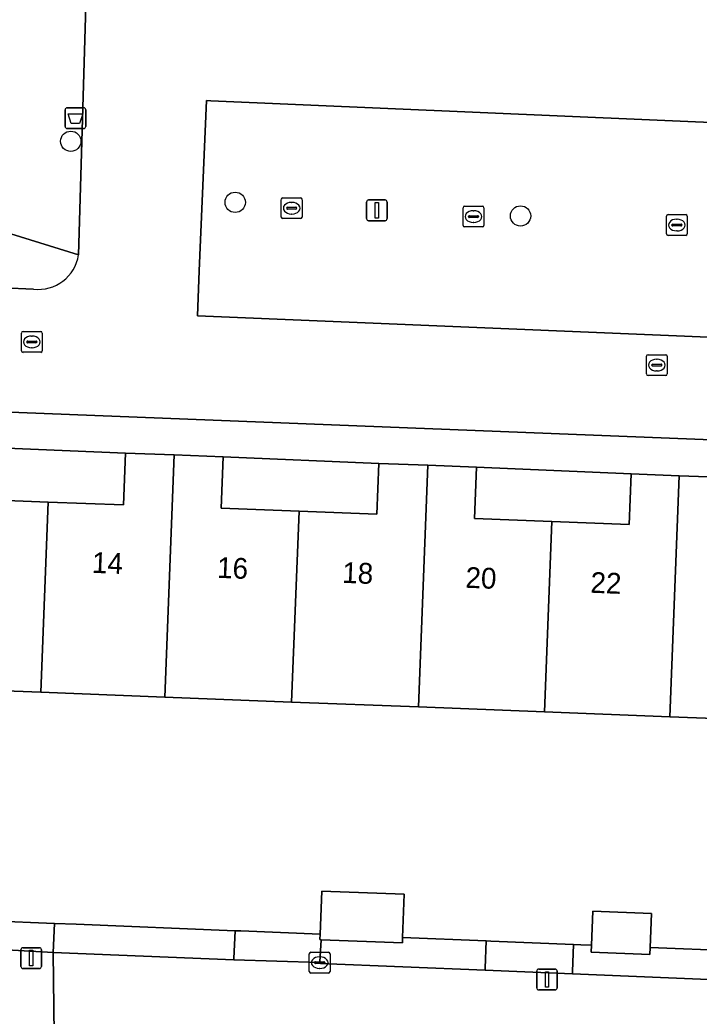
# Model space of a CAD drawing. Extents: x 160786 to 161429, y 386828 to 387485.
# Drawn here: x 161040.54 to 161073.22, y 387264.64 to 387312.56 of the extents above; entities that cross this region are included whole.
import ezdxf

# ---------------------------------------------------------------- set-up
doc = ezdxf.new("R2010")
doc.units = 0
for name, color, linetype in [('IMGEO_Afvalbak', 7, 'Continuous'), ('IMGEO_Boom', 7, 'Continuous'), ('IMGEO_Erf', 7, 'Continuous'), ('IMGEO_Groenvoorziening', 7, 'Continuous'), ('IMGEO_Kolk', 7, 'Continuous'), ('IMGEO_Lichtmast', 7, 'Continuous'), ('IMGEO_Pand', 7, 'Continuous'), ('IMGEO_Pand_nummerreeks', 7, 'Continuous'), ('IMGEO_Parkeervlak_open', 7, 'Continuous'), ('IMGEO_Rioolput', 7, 'Continuous'), ('IMGEO_Voetpad_open', 7, 'Continuous')]:
    doc.layers.add(name, color=color, linetype=linetype)

msp = doc.modelspace()

# ---------------------------------------------------------------- linework, layer by layer
at = {"layer": 'IMGEO_Afvalbak'}
for p, q in [((161042.718, 387307.44), (161042.718, 387308.24)), ((161042.718, 387308.24), (161042.718, 387307.44)), ((161042.818, 387308.34), (161043.608, 387308.34)), ((161043.608, 387308.34), (161042.818, 387308.34)), ((161043.708, 387308.24), (161043.708, 387307.44)), ((161043.708, 387307.44), (161043.708, 387308.24)), ((161043.608, 387307.34), (161042.818, 387307.34)), ((161042.818, 387307.34), (161043.608, 387307.34))]:
    msp.add_line(p, q, dxfattribs=at)
msp.add_lwpolyline([(161042.861, 387308.054), (161043.565, 387308.054), (161043.416, 387307.584), (161043.01, 387307.584), (161042.861, 387308.054)], dxfattribs=at)
for centre, start, end in [((161042.818, 387308.24), 90, 180), ((161042.818, 387308.24), 90, 180), ((161043.608, 387308.24), 0, 90), ((161043.608, 387308.24), 360, 90), ((161042.818, 387307.44), 180, 270), ((161042.818, 387307.44), 180, 270), ((161043.608, 387307.44), 270, 0), ((161043.608, 387307.44), 270, 0)]:
    msp.add_arc(centre, 0.1, start, end, dxfattribs=at)
at = {"layer": 'IMGEO_Boom'}
for centre in [(161042.988, 387306.725), (161050.899, 387303.788), (161064.629, 387303.133)]:
    msp.add_circle(centre, 0.489, dxfattribs=at)
at = {"layer": 'IMGEO_Erf'}
for points in [[(161038.374, 387292.034), (161038.276, 387289.514), (161041.898, 387289.372), (161045.518, 387289.231), (161045.615, 387291.726)], [(161050.318, 387291.542), (161050.222, 387289.075), (161053.97, 387288.928), (161057.718, 387288.782), (161057.814, 387291.229)], [(161062.516, 387291.045), (161062.42, 387288.576), (161066.138, 387288.431), (161069.857, 387288.286), (161069.952, 387290.729)]]:
    msp.add_lwpolyline(points, close=True, dxfattribs=at)
for points in [[(161101.692, 387277.875), (161095.739, 387278.107), (161089.782, 387278.339), (161083.812, 387278.572), (161077.787, 387278.807), (161071.808, 387279.04), (161065.781, 387279.275), (161059.712, 387279.512), (161053.612, 387279.75), (161047.514, 387279.988), (161041.541, 387280.221), (161035.537, 387280.455), (161035.313, 387280.464), (161035.188, 387277.258), (161029.377, 387277.484), (161029.502, 387280.69), (161023.521, 387280.923), (161017.529, 387281.157), (161011.527, 387281.391), (161011.389, 387277.862), (161005.238, 387278.102), (161005.045, 387271.345)], [(161039.126, 387269.225), (161042.204, 387269.1), (161043.253, 387269.058), (161050.892, 387268.747), (161051.177, 387268.736), (161054.984, 387268.581), (161055.065, 387270.654), (161059.035, 387270.499), (161058.953, 387268.42), (161062.977, 387268.257), (161063.197, 387268.248), (161067.18, 387268.086), (161067.524, 387268.072), (161068.036, 387268.051), (161068.1, 387269.689), (161070.927, 387269.579), (161070.863, 387267.936), (161074.883, 387267.773)]]:
    msp.add_lwpolyline(points, dxfattribs=at)
at = {"layer": 'IMGEO_Groenvoorziening'}
for points in [[(161050.892, 387268.747), (161043.253, 387269.058), (161042.204, 387269.1), (161042.15, 387267.701), (161050.837, 387267.344), (161050.84, 387267.414)], [(161062.977, 387268.257), (161058.953, 387268.42), (161058.943, 387268.163), (161055.037, 387268.316), (161054.968, 387267.254), (161054.965, 387267.213), (161055, 387267.174), (161062.922, 387266.848), (161062.926, 387266.944)], [(161074.883, 387267.773), (161070.863, 387267.936), (161070.85, 387267.611), (161068.023, 387267.721), (161068.036, 387268.051), (161067.524, 387268.072), (161067.18, 387268.086), (161067.127, 387266.78), (161067.122, 387266.676), (161074.828, 387266.36), (161074.832, 387266.481)]]:
    msp.add_lwpolyline(points, close=True, dxfattribs=at)
at = {"layer": 'IMGEO_Kolk'}
for p, q in [((161053.117, 387303.081), (161053.117, 387303.933)), ((161053.192, 387304.007), (161054.044, 387304.007)), ((161054.118, 387303.933), (161054.118, 387303.081)), ((161053.376, 387303.501), (161053.376, 387303.513)), ((161053.814, 387303.464), (161053.416, 387303.464)), ((161053.419, 387303.55), (161053.817, 387303.55)), ((161053.605, 387303.787), (161053.63, 387303.787)), ((161053.86, 387303.513), (161053.86, 387303.501)), ((161061.864, 387302.677), (161061.864, 387303.529)), ((161061.939, 387303.603), (161062.791, 387303.603)), ((161062.865, 387303.529), (161062.865, 387302.677)), ((161054.044, 387303.007), (161053.192, 387303.007)), ((161053.628, 387303.227), (161053.603, 387303.227)), ((161062.123, 387303.097), (161062.123, 387303.109)), ((161062.561, 387303.06), (161062.163, 387303.06)), ((161062.166, 387303.146), (161062.564, 387303.146)), ((161062.352, 387303.383), (161062.377, 387303.383)), ((161062.607, 387303.109), (161062.607, 387303.097)), ((161071.652, 387302.27), (161071.652, 387303.122)), ((161071.727, 387303.196), (161072.579, 387303.196)), ((161072.14, 387302.976), (161072.165, 387302.976)), ((161072.653, 387303.122), (161072.653, 387302.27)), ((161062.791, 387302.603), (161061.939, 387302.603)), ((161062.375, 387302.823), (161062.35, 387302.823)), ((161071.911, 387302.69), (161071.911, 387302.702)), ((161072.349, 387302.653), (161071.951, 387302.653)), ((161071.954, 387302.739), (161072.352, 387302.739)), ((161072.395, 387302.702), (161072.395, 387302.69)), ((161072.579, 387302.196), (161071.727, 387302.196)), ((161072.163, 387302.416), (161072.138, 387302.416)), ((161054.464, 387266.787), (161054.464, 387267.639)), ((161054.539, 387267.713), (161055.391, 387267.713)), ((161054.952, 387267.493), (161054.977, 387267.493)), ((161055.465, 387267.639), (161055.465, 387266.787)), ((161054.723, 387267.207), (161054.723, 387267.219)), ((161055.161, 387267.17), (161054.763, 387267.17)), ((161054.766, 387267.256), (161055.164, 387267.256)), ((161055.207, 387267.219), (161055.207, 387267.207)), ((161055.391, 387266.713), (161054.539, 387266.713)), ((161054.975, 387266.933), (161054.95, 387266.933))]:
    msp.add_line(p, q, dxfattribs=at)
for points in [[(161053.117, 387303.081), (161053.117, 387303.933)], [(161053.192, 387304.007), (161054.044, 387304.007)], [(161054.118, 387303.933), (161054.118, 387303.081)], [(161061.864, 387302.677), (161061.864, 387303.529)], [(161061.939, 387303.603), (161062.791, 387303.603)], [(161062.865, 387303.529), (161062.865, 387302.677)], [(161054.044, 387303.007), (161053.192, 387303.007)], [(161071.652, 387302.27), (161071.652, 387303.122)], [(161071.727, 387303.196), (161072.579, 387303.196)], [(161072.653, 387303.122), (161072.653, 387302.27)], [(161062.791, 387302.603), (161061.939, 387302.603)], [(161072.579, 387302.196), (161071.727, 387302.196)], [(161054.464, 387266.787), (161054.464, 387267.639)], [(161054.539, 387267.713), (161055.391, 387267.713)], [(161055.465, 387267.639), (161055.465, 387266.787)], [(161055.391, 387266.713), (161054.539, 387266.713)]]:
    msp.add_lwpolyline(points, dxfattribs=at)
for centre, radius, start, end in [((161053.194, 387303.931), 0.0765, 91.552, 178.448), ((161053.194, 387303.931), 0.0765, 91.552, 178.448), ((161054.042, 387303.931), 0.0765, 1.552, 88.448), ((161054.042, 387303.931), 0.0765, 1.552, 88.448), ((161053.416, 387303.51), 0.0403, 85.8775, 175.7526), ((161053.413, 387303.5), 0.0366, 178.938, 274.7102), ((161053.817, 387303.507), 0.043, 264.8664, 352.4533), ((161053.821, 387303.512), 0.0386, 1.7309, 96.639), ((161061.941, 387303.527), 0.0765, 91.552, 178.448), ((161061.941, 387303.527), 0.0765, 91.552, 178.448), ((161062.789, 387303.527), 0.0765, 1.552, 88.448), ((161062.789, 387303.527), 0.0765, 1.552, 88.448), ((161053.194, 387303.083), 0.0765, 181.552, 268.448), ((161053.194, 387303.083), 0.0765, 181.552, 268.448), ((161054.042, 387303.083), 0.0765, 271.552, 358.448), ((161054.042, 387303.083), 0.0765, 271.552, 358.448), ((161062.163, 387303.106), 0.0403, 85.8775, 175.7526), ((161062.16, 387303.096), 0.0366, 178.938, 274.7102), ((161062.564, 387303.103), 0.043, 264.8664, 352.4533), ((161062.568, 387303.108), 0.0386, 1.7309, 96.639), ((161071.729, 387303.12), 0.0765, 91.552, 178.448), ((161071.729, 387303.12), 0.0765, 91.552, 178.448), ((161072.577, 387303.12), 0.0765, 1.552, 88.448), ((161072.577, 387303.12), 0.0765, 1.552, 88.448), ((161061.941, 387302.679), 0.0765, 181.552, 268.448), ((161061.941, 387302.679), 0.0765, 181.552, 268.448), ((161062.789, 387302.679), 0.0765, 271.552, 358.448), ((161062.789, 387302.679), 0.0765, 271.552, 358.448), ((161071.951, 387302.699), 0.0403, 85.8775, 175.7526), ((161071.948, 387302.689), 0.0366, 178.938, 274.7102), ((161072.352, 387302.696), 0.043, 264.8664, 352.4533), ((161072.356, 387302.701), 0.0386, 1.7309, 96.639), ((161071.729, 387302.272), 0.0765, 181.552, 268.448), ((161071.729, 387302.272), 0.0765, 181.552, 268.448), ((161072.577, 387302.272), 0.0765, 271.552, 358.448), ((161072.577, 387302.272), 0.0765, 271.552, 358.448), ((161054.541, 387267.637), 0.0765, 91.552, 178.448), ((161054.541, 387267.637), 0.0765, 91.552, 178.448), ((161055.389, 387267.637), 0.0765, 1.552, 88.448), ((161055.389, 387267.637), 0.0765, 1.552, 88.448), ((161054.763, 387267.216), 0.0403, 85.8775, 175.7526), ((161054.76, 387267.206), 0.0366, 178.938, 274.7102), ((161055.164, 387267.213), 0.043, 264.8664, 352.4533), ((161055.168, 387267.218), 0.0386, 1.7309, 96.639), ((161054.541, 387266.789), 0.0765, 181.552, 268.448), ((161054.541, 387266.789), 0.0765, 181.552, 268.448), ((161055.389, 387266.789), 0.0765, 271.552, 358.448), ((161055.389, 387266.789), 0.0765, 271.552, 358.448)]:
    msp.add_arc(centre, radius, start, end, dxfattribs=at)
for centre, major_axis, ratio, start_param, end_param in [((161053.604, 387303.507), (-0.387, 0.002), 0.722429, 4.712389, 7.853982), ((161053.629, 387303.507), (-0.39, 0.002), 0.717154, 1.570796, 4.712389), ((161062.351, 387303.103), (-0.387, 0.002), 0.722429, 4.712389, 7.853982), ((161062.376, 387303.103), (-0.39, 0.002), 0.717154, 1.570796, 4.712389), ((161072.139, 387302.696), (-0.387, 0.002), 0.722429, 4.712389, 7.853982), ((161072.164, 387302.696), (-0.39, 0.002), 0.717154, 1.570796, 4.712389), ((161054.951, 387267.213), (-0.387, 0.002), 0.722429, 4.712389, 7.853982), ((161054.976, 387267.213), (-0.39, 0.002), 0.717154, 1.570796, 4.712389)]:
    msp.add_ellipse(centre, major_axis=major_axis, ratio=ratio, start_param=start_param, end_param=end_param, dxfattribs=at)
at = {"layer": 'IMGEO_Lichtmast'}
for p, q in [((161057.321, 387303.903), (161058.111, 387303.903)), ((161058.111, 387303.903), (161057.321, 387303.903)), ((161057.221, 387303.003), (161057.221, 387303.803)), ((161057.221, 387303.803), (161057.221, 387303.003)), ((161058.211, 387303.803), (161058.211, 387303.003)), ((161058.211, 387303.003), (161058.211, 387303.803)), ((161058.111, 387302.903), (161057.321, 387302.903)), ((161057.321, 387302.903), (161058.111, 387302.903)), ((161040.589, 387267.03), (161040.589, 387267.83)), ((161040.589, 387267.83), (161040.589, 387267.03)), ((161040.689, 387267.93), (161041.479, 387267.93)), ((161041.479, 387267.93), (161040.689, 387267.93)), ((161041.579, 387267.83), (161041.579, 387267.03)), ((161041.579, 387267.03), (161041.579, 387267.83)), ((161041.479, 387266.93), (161040.689, 387266.93)), ((161040.689, 387266.93), (161041.479, 387266.93)), ((161065.405, 387266), (161065.405, 387266.8)), ((161065.405, 387266.8), (161065.405, 387266)), ((161065.505, 387266.9), (161066.295, 387266.9)), ((161066.295, 387266.9), (161065.505, 387266.9)), ((161066.395, 387266.8), (161066.395, 387266)), ((161066.395, 387266), (161066.395, 387266.8)), ((161066.295, 387265.9), (161065.505, 387265.9)), ((161065.505, 387265.9), (161066.295, 387265.9))]:
    msp.add_line(p, q, dxfattribs=at)
for points in [[(161057.641, 387303.778), (161057.791, 387303.778), (161057.791, 387303.028), (161057.641, 387303.028), (161057.641, 387303.778)], [(161041.009, 387267.805), (161041.159, 387267.805), (161041.159, 387267.055), (161041.009, 387267.055), (161041.009, 387267.805)], [(161065.825, 387266.775), (161065.975, 387266.775), (161065.975, 387266.025), (161065.825, 387266.025), (161065.825, 387266.775)]]:
    msp.add_lwpolyline(points, dxfattribs=at)
for centre, start, end in [((161057.321, 387303.803), 90, 180), ((161057.321, 387303.803), 90, 180), ((161058.111, 387303.803), 0, 90), ((161058.111, 387303.803), 360, 90), ((161057.321, 387303.003), 180, 270), ((161057.321, 387303.003), 180, 270), ((161058.111, 387303.003), 270, 0), ((161058.111, 387303.003), 270, 0), ((161040.689, 387267.83), 90, 180), ((161040.689, 387267.83), 90, 180), ((161041.479, 387267.83), 0, 90), ((161041.479, 387267.83), 360, 90), ((161040.689, 387267.03), 180, 270), ((161040.689, 387267.03), 180, 270), ((161041.479, 387267.03), 270, 0), ((161041.479, 387267.03), 270, 0), ((161065.505, 387266.8), 90, 180), ((161065.505, 387266.8), 90, 180), ((161066.295, 387266.8), 0, 90), ((161066.295, 387266.8), 360, 90), ((161065.505, 387266), 180, 270), ((161065.505, 387266), 180, 270), ((161066.295, 387266), 270, 0), ((161066.295, 387266), 270, 0)]:
    msp.add_arc(centre, 0.1, start, end, dxfattribs=at)
at = {"layer": 'IMGEO_Pand'}
for points in [[(161035.992, 387292.127), (161035.537, 387280.455), (161041.541, 387280.221), (161041.898, 387289.372), (161038.276, 387289.514), (161038.374, 387292.034)], [(161045.615, 387291.726), (161045.518, 387289.231), (161041.898, 387289.372), (161041.541, 387280.221), (161047.514, 387279.988), (161047.968, 387291.634)], [(161047.968, 387291.634), (161047.514, 387279.988), (161053.612, 387279.75), (161053.97, 387288.928), (161050.222, 387289.075), (161050.318, 387291.542)], [(161057.814, 387291.229), (161057.718, 387288.782), (161053.97, 387288.928), (161053.612, 387279.75), (161059.712, 387279.512), (161060.165, 387291.137)], [(161060.165, 387291.137), (161059.712, 387279.512), (161065.781, 387279.275), (161066.138, 387288.431), (161062.42, 387288.576), (161062.516, 387291.045)], [(161069.952, 387290.729), (161069.857, 387288.286), (161066.138, 387288.431), (161065.781, 387279.275), (161071.808, 387279.04), (161072.26, 387290.639)], [(161072.26, 387290.639), (161071.808, 387279.04), (161077.787, 387278.807), (161078.142, 387287.905), (161074.471, 387288.048), (161074.568, 387290.549)], [(161054.984, 387268.581), (161054.974, 387268.318), (161055.037, 387268.316), (161058.943, 387268.163), (161058.953, 387268.42), (161059.035, 387270.499), (161055.065, 387270.654)], [(161068.036, 387268.051), (161068.023, 387267.721), (161070.85, 387267.611), (161070.863, 387267.936), (161070.927, 387269.579), (161068.1, 387269.689)]]:
    msp.add_lwpolyline(points, close=True, dxfattribs=at)
at = {"layer": 'IMGEO_Parkeervlak_open'}
msp.add_lwpolyline([(161096.75, 387306.632), (161049.733, 387308.677), (161049.512, 387308.687), (161049.17, 387300.494), (161049.08, 387298.333), (161096.316, 387296.364), (161096.407, 387298.525)], close=True, dxfattribs=at)
at = {"layer": 'IMGEO_Rioolput'}
for p, q in [((161040.617, 387296.647), (161040.617, 387297.499)), ((161040.692, 387297.573), (161041.544, 387297.573)), ((161041.105, 387297.353), (161041.13, 387297.353)), ((161041.618, 387297.499), (161041.618, 387296.647)), ((161040.876, 387297.067), (161040.876, 387297.079)), ((161041.314, 387297.03), (161040.916, 387297.03)), ((161040.919, 387297.116), (161041.317, 387297.116)), ((161041.128, 387296.793), (161041.103, 387296.793)), ((161041.36, 387297.079), (161041.36, 387297.067)), ((161041.544, 387296.573), (161040.692, 387296.573)), ((161070.688, 387295.532), (161070.688, 387296.384)), ((161070.763, 387296.458), (161071.615, 387296.458)), ((161071.176, 387296.238), (161071.201, 387296.238)), ((161071.689, 387296.384), (161071.689, 387295.532)), ((161070.947, 387295.952), (161070.947, 387295.964)), ((161071.385, 387295.915), (161070.987, 387295.915)), ((161070.99, 387296.001), (161071.388, 387296.001)), ((161071.431, 387295.964), (161071.431, 387295.952)), ((161071.615, 387295.458), (161070.763, 387295.458)), ((161071.199, 387295.678), (161071.174, 387295.678))]:
    msp.add_line(p, q, dxfattribs=at)
for points in [[(161040.617, 387296.647), (161040.617, 387297.499)], [(161040.692, 387297.573), (161041.544, 387297.573)], [(161041.618, 387297.499), (161041.618, 387296.647)], [(161041.544, 387296.573), (161040.692, 387296.573)], [(161070.688, 387295.532), (161070.688, 387296.384)], [(161070.763, 387296.458), (161071.615, 387296.458)], [(161071.689, 387296.384), (161071.689, 387295.532)], [(161071.615, 387295.458), (161070.763, 387295.458)]]:
    msp.add_lwpolyline(points, dxfattribs=at)
for centre, radius, start, end in [((161040.694, 387297.497), 0.0765, 91.552, 178.448), ((161040.694, 387297.497), 0.0765, 91.552, 178.448), ((161041.542, 387297.497), 0.0765, 1.552, 88.448), ((161041.542, 387297.497), 0.0765, 1.552, 88.448), ((161040.916, 387297.076), 0.0403, 85.8775, 175.7526), ((161040.913, 387297.066), 0.0366, 178.938, 274.7102), ((161041.317, 387297.073), 0.043, 264.8664, 352.4533), ((161041.321, 387297.078), 0.0386, 1.7309, 96.639), ((161040.694, 387296.649), 0.0765, 181.552, 268.448), ((161040.694, 387296.649), 0.0765, 181.552, 268.448), ((161041.542, 387296.649), 0.0765, 271.552, 358.448), ((161041.542, 387296.649), 0.0765, 271.552, 358.448), ((161070.765, 387296.382), 0.0765, 91.552, 178.448), ((161070.765, 387296.382), 0.0765, 91.552, 178.448), ((161071.613, 387296.382), 0.0765, 1.552, 88.448), ((161071.613, 387296.382), 0.0765, 1.552, 88.448), ((161070.987, 387295.961), 0.0403, 85.8775, 175.7526), ((161070.984, 387295.951), 0.0366, 178.938, 274.7102), ((161071.388, 387295.958), 0.043, 264.8664, 352.4533), ((161071.392, 387295.963), 0.0386, 1.7309, 96.639), ((161070.765, 387295.534), 0.0765, 181.552, 268.448), ((161070.765, 387295.534), 0.0765, 181.552, 268.448), ((161071.613, 387295.534), 0.0765, 271.552, 358.448), ((161071.613, 387295.534), 0.0765, 271.552, 358.448)]:
    msp.add_arc(centre, radius, start, end, dxfattribs=at)
for centre, major_axis, ratio, start_param, end_param in [((161041.104, 387297.073), (-0.387, 0.002), 0.722429, 4.712389, 7.853982), ((161041.129, 387297.073), (-0.39, 0.002), 0.717154, 1.570796, 4.712389), ((161071.175, 387295.958), (-0.387, 0.002), 0.722429, 4.712389, 7.853982), ((161071.2, 387295.958), (-0.39, 0.002), 0.717154, 1.570796, 4.712389)]:
    msp.add_ellipse(centre, major_axis=major_axis, ratio=ratio, start_param=start_param, end_param=end_param, dxfattribs=at)
at = {"layer": 'IMGEO_Voetpad_open'}
for points in [[(161039.62, 387353.354), (161039.478, 387348.98), (161039.295, 387343.281), (161039.449, 387343.275), (161039.197, 387337.059), (161039.04, 387333.18), (161038.733, 387326.037), (161038.563, 387321.838), (161038.281, 387314.709), (161038.112, 387310.547), (161037.77, 387302.999), (161043.36, 387301.265), (161043.754, 387314.896), (161044.012, 387320.912), (161044.322, 387328.28), (161044.504, 387332.513), (161044.752, 387339.564)], [(161101.064, 387312.508), (161098.379, 387312.62), (161095.312, 387312.75), (161092.245, 387312.879), (161089.178, 387313.009), (161086.111, 387313.138), (161083.043, 387313.268), (161079.976, 387313.398), (161076.909, 387313.527), (161073.842, 387313.657), (161068.329, 387313.841), (161065.257, 387313.973), (161062.185, 387314.105), (161059.113, 387314.237), (161056.042, 387314.368), (161052.97, 387314.5), (161049.898, 387314.632), (161046.826, 387314.764), (161043.754, 387314.896), (161043.36, 387301.265)], [(160941.896, 387303.713), (160942.394, 387303.693), (160943.923, 387303.63), (160944.555, 387303.604), (161003.427, 387301.192), (161007.761, 387301.014), (161007.976, 387301.005), (161010.337, 387300.909), (161010.458, 387300.904), (161015.08, 387300.714), (161031.068, 387300.048), (161031.396, 387300.034), (161033.794, 387299.932), (161033.89, 387299.928), (161041.191, 387299.617)], [(161043.36, 387301.265), (161037.77, 387302.999), (161030.392, 387303.382)], [(161041.191, 387299.617), (161033.89, 387299.928), (161033.794, 387299.932), (161033.563, 387294.053), (161033.559, 387293.946), (161100.662, 387291.305)], [(161100.662, 387291.305), (161033.559, 387293.946), (161030.833, 387294.053)], [(161038.374, 387292.034), (161045.615, 387291.726), (161047.968, 387291.634), (161050.318, 387291.542), (161057.814, 387291.229), (161060.165, 387291.137), (161062.516, 387291.045), (161069.952, 387290.729), (161072.26, 387290.639), (161074.568, 387290.549), (161081.915, 387290.273), (161084.265, 387290.182), (161086.617, 387290.09), (161093.847, 387289.756), (161096.19, 387289.665), (161098.533, 387289.573), (161102.179, 387289.436), (161102.212, 387292.628)], [(161041.819, 387250.786), (161041.992, 387254.976), (161042.243, 387259.778), (161042.242, 387259.789), (161042.15, 387267.701), (161039.07, 387267.871), (161031.266, 387268.175), (161030.819, 387268.192), (161027.059, 387268.338), (161019.035, 387268.65), (161014.949, 387268.809), (161007.11, 387269.114)], [(161104.687, 387263.019), (161104.6, 387263.164), (161104.526, 387263.317), (161104.465, 387263.476), (161104.42, 387263.639), (161104.389, 387263.806), (161104.373, 387263.974), (161104.372, 387264.144), (161104.419, 387265.337), (161099.828, 387265.381), (161099.086, 387265.364), (161090.722, 387265.707), (161086.994, 387265.86), (161078.768, 387266.198), (161074.828, 387266.36), (161067.122, 387266.676), (161062.922, 387266.848), (161055, 387267.174), (161054.965, 387267.213), (161050.837, 387267.344), (161042.15, 387267.701), (161042.242, 387259.789), (161042.243, 387259.778)]]:
    msp.add_lwpolyline(points, dxfattribs=at)
for points in [[(161096.75, 387306.632), (161096.407, 387298.525), (161096.316, 387296.364), (161049.08, 387298.333), (161049.17, 387300.494), (161049.512, 387308.687), (161049.733, 387308.677)], [(161042.204, 387269.1), (161039.126, 387269.225), (161039.07, 387267.871), (161042.15, 387267.701)], [(161055.037, 387268.316), (161054.974, 387268.318), (161054.984, 387268.581), (161051.177, 387268.736), (161050.892, 387268.747), (161050.84, 387267.414), (161050.837, 387267.344), (161054.965, 387267.213), (161054.968, 387267.254)], [(161067.18, 387268.086), (161063.197, 387268.248), (161062.977, 387268.257), (161062.926, 387266.944), (161062.922, 387266.848), (161067.122, 387266.676), (161067.127, 387266.78)]]:
    msp.add_lwpolyline(points, close=True, dxfattribs=at)
msp.add_arc((161041.438, 387301.544), 1.942, 262.7011, 351.7539, dxfattribs=at)
msp.add_arc((161041.438, 387301.544), 1.942, 262.7011, 351.7539, dxfattribs=at)

# ---------------------------------------------------------------- texts
at = {"layer": 'IMGEO_Pand_nummerreeks'}
for s, p in [('14', (161043.993, 387285.967)), ('16', (161050.013, 387285.727)), ('18', (161056.035, 387285.486)), ('20', (161061.964, 387285.249)), ('22', (161067.978, 387285.009))]:
    msp.add_text(s, height=1, rotation=357.7109, dxfattribs=at).set_placement(p)

doc.saveas('drawing.dxf')
